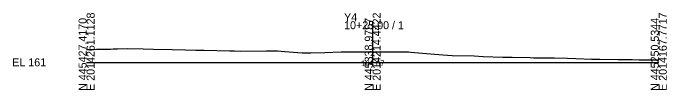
# Model space of a CAD drawing. Extents: x -26 to 203, y -10 to 4021.
# Drawn here: x -25.7 to 202.8, y 490.3 to 517.3 of the extents above; entities that cross this region are included whole.
import ezdxf

# ---------------------------------------------------------------- set-up
doc = ezdxf.new("R2010")
doc.units = 0
for name, color, linetype in [('Default', 7, 'Continuous'), ('Exist Cross Section Cell', 7, 'Continuous'), ('Exist XS Center Line Elevation Label', 7, 'Continuous'), ('Exist XS Ground Line', 7, 'Continuous')]:
    doc.layers.add(name, color=color, linetype=linetype)

msp = doc.modelspace()

# ---------------------------------------------------------------- linework, layer by layer
at = {"layer": 'Exist Cross Section Cell'}
for p, q in [((100, 500), (100, 514.45)), ((0, 500), (100, 500)), ((100, 500), (200, 500))]:
    msp.add_line(p, q, dxfattribs=at)
at = {"layer": 'Exist XS Ground Line'}
msp.add_lwpolyline([(0, 504.51), (1.02, 504.53), (2.68, 504.56), (3.5, 504.58), (5.46, 504.62), (6.86, 504.65), (8.34, 504.69), (9.25, 504.71), (10.35, 504.74), (10.83, 504.75), (14.22, 504.82), (19.82, 504.7), (23.35, 504.64), (29.88, 504.51), (34.62, 504.41), (38.2, 504.33), (41, 504.26), (50.02, 504.06), (51.72, 504.01), (53.9, 503.95), (62.93, 504.01), (66.68, 503.99), (69.29, 503.84), (75.33, 503.34), (75.87, 503.33), (76.47, 503.3), (78.41, 503.33), (83.23, 503.46), (88.99, 503.7), (91.3, 503.71), (100.04, 503.67), (112.49, 503.65), (113.31, 503.63), (114.6, 503.51), (120.19, 502.99), (124.57, 502.59), (127.77, 502.39), (135.5, 502.24), (138.67, 502.08), (145.44, 501.84), (148.74, 501.81), (155, 501.66), (156.15, 501.64), (156.75, 501.62), (163.55, 501.57), (168.06, 501.49), (170.95, 501.4), (176.43, 501.17), (179.37, 501.08), (185.75, 501.05), (190.67, 500.97), (193.16, 500.91), (197.86, 500.88), (200, 500.85)], dxfattribs=at)

# ---------------------------------------------------------------- texts
at = {"layer": 'Default'}
msp.add_text('-', height=0.0001, dxfattribs=at).set_placement((0, 500))
at = {"layer": 'Exist Cross Section Cell'}
for s, p in [('E 2014261.1128', (2.8, 490)), ('E 2014214.4422', (102.8, 490)), ('E 2014167.7717', (202.8, 490)), ('N 445427.4170', (0, 490)), ('N 445338.9757', (100, 490)), ('N 445250.5344', (200, 490))]:
    msp.add_text(s, height=2.8, rotation=90, dxfattribs=at).set_placement(p)
for s, p in [('Y4', (90, 514.45)), ('10+25.00 / 1', (90, 511.65)), ('EL 161', (-26, 498.6))]:
    msp.add_text(s, height=2.8, dxfattribs=at).set_placement(p)
at = {"layer": 'Exist XS Center Line Elevation Label'}
msp.add_text('164.67', height=2, dxfattribs=at).set_placement((95.94, 498.67))

doc.saveas('drawing.dxf')
